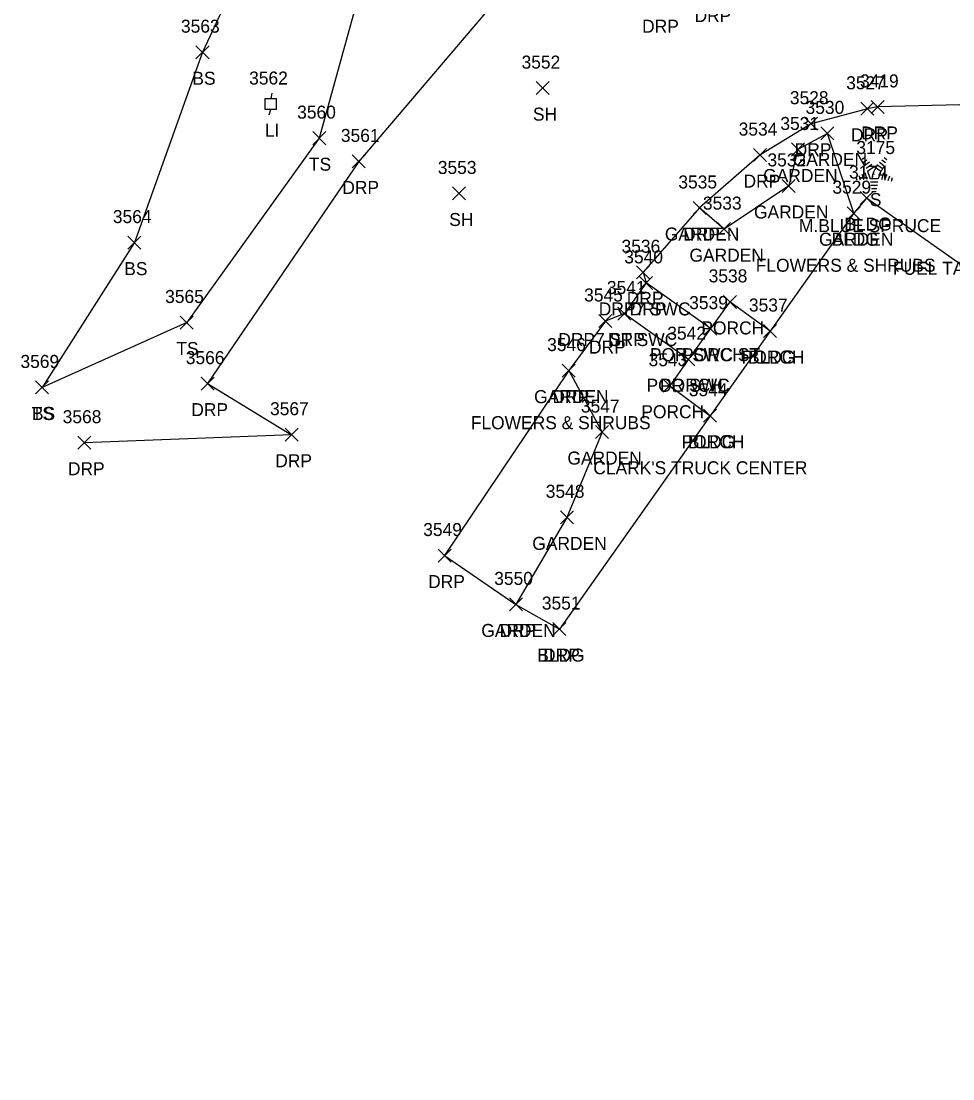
# Model space of a CAD drawing. Extents: x 1520648 to 1523413, y 732854 to 735518.
# Drawn here: x 1521497.2 to 1521640.4, y 733371.2 to 733533.8 of the extents above; entities that cross this region are included whole.
import ezdxf

# ---------------------------------------------------------------- set-up
doc = ezdxf.new("R2010")
doc.units = 0
for name, color, linetype in [('L_A', 7, 'Continuous'), ('L_C', 7, 'Continuous'), ('L_I', 7, 'Continuous'), ('L_TIC', 7, 'Continuous'), ('LAPB', 7, 'Continuous'), ('LBC', 7, 'Continuous'), ('LBF', 7, 'Continuous'), ('LELB', 7, 'Continuous'), ('LTC', 7, 'Continuous'), ('R_A', 7, 'Continuous'), ('R_C', 7, 'Continuous'), ('R_I', 7, 'Continuous'), ('R_TIC', 7, 'Continuous'), ('RDP', 7, 'Continuous'), ('RSW', 7, 'Continuous'), ('U_A', 7, 'Continuous'), ('U_C', 7, 'Continuous'), ('U_I', 7, 'Continuous'), ('ULP', 7, 'Continuous')]:
    doc.layers.add(name, color=color, linetype=linetype)

msp = doc.modelspace()

# ---------------------------------------------------------------- linework, layer by layer
at = {"layer": 'L_TIC'}
for points in [[(1521524.06, 733528.01), (1521526.06, 733530.01)], [(1521526.06, 733528.01), (1521524.06, 733530.01)], [(1521576.36, 733522.49), (1521578.36, 733524.49)], [(1521578.36, 733522.49), (1521576.36, 733524.49)], [(1521542.01, 733514.8), (1521544.01, 733516.8)], [(1521544.01, 733514.8), (1521542.01, 733516.8)], [(1521620.11, 733515.53), (1521622.11, 733517.53)], [(1521622.11, 733515.53), (1521620.11, 733517.53)], [(1521615.58, 733513.06), (1521617.58, 733515.06)], [(1521617.58, 733513.06), (1521615.58, 733515.06)], [(1521614.16, 733507.46), (1521616.16, 733509.46)], [(1521616.16, 733507.46), (1521614.16, 733509.46)], [(1521563.49, 733506.3), (1521565.49, 733508.3)], [(1521565.49, 733506.3), (1521563.49, 733508.3)], [(1521626.13, 733505.6), (1521628.13, 733507.6)], [(1521628.13, 733505.6), (1521626.13, 733507.6)], [(1521600.46, 733504.07), (1521602.46, 733506.07)], [(1521602.46, 733504.07), (1521600.46, 733506.07)], [(1521624.15, 733503.27), (1521626.15, 733505.27)], [(1521626.15, 733503.27), (1521624.15, 733505.27)], [(1521624.15, 733503.27), (1521626.15, 733505.27)], [(1521626.15, 733503.27), (1521624.15, 733505.27)], [(1521604.24, 733500.82), (1521606.24, 733502.82)], [(1521606.24, 733500.82), (1521604.24, 733502.82)], [(1521513.59, 733498.75), (1521515.59, 733500.75)], [(1521515.59, 733498.75), (1521513.59, 733500.75)], [(1521605.12, 733489.64), (1521607.12, 733491.64)], [(1521607.12, 733489.64), (1521605.12, 733491.64)], [(1521521.63, 733486.47), (1521523.63, 733488.47)], [(1521523.63, 733486.47), (1521521.63, 733488.47)], [(1521602.14, 733485.53), (1521604.14, 733487.53)], [(1521604.14, 733485.53), (1521602.14, 733487.53)], [(1521611.31, 733485.16), (1521613.31, 733487.16)], [(1521613.31, 733485.16), (1521611.31, 733487.16)], [(1521611.31, 733485.16), (1521613.31, 733487.16)], [(1521613.31, 733485.16), (1521611.31, 733487.16)], [(1521598.76, 733480.83), (1521600.76, 733482.83)], [(1521600.76, 733480.83), (1521598.76, 733482.83)], [(1521580.36, 733479.08), (1521582.36, 733481.08)], [(1521582.36, 733479.08), (1521580.36, 733481.08)], [(1521499.4, 733476.49), (1521501.4, 733478.49)], [(1521501.4, 733476.49), (1521499.4, 733478.49)], [(1521499.4, 733476.49), (1521501.4, 733478.49)], [(1521501.4, 733476.49), (1521499.4, 733478.49)], [(1521595.89, 733476.76), (1521597.89, 733478.76)], [(1521597.89, 733476.76), (1521595.89, 733478.76)], [(1521602.07, 733472.15), (1521604.07, 733474.15)], [(1521604.07, 733472.15), (1521602.07, 733474.15)], [(1521602.07, 733472.15), (1521604.07, 733474.15)], [(1521604.07, 733472.15), (1521602.07, 733474.15)], [(1521585.48, 733469.64), (1521587.48, 733471.64)], [(1521587.48, 733469.64), (1521585.48, 733471.64)], [(1521580.08, 733456.53), (1521582.08, 733458.53)], [(1521582.08, 733456.53), (1521580.08, 733458.53)], [(1521572.24, 733443.15), (1521574.24, 733445.15)], [(1521574.24, 733443.15), (1521572.24, 733445.15)], [(1521578.92, 733439.36), (1521580.92, 733441.36)], [(1521580.92, 733439.36), (1521578.92, 733441.36)]]:
    msp.add_lwpolyline(points, dxfattribs=at)
at = {"layer": 'LAPB'}
for points in [[(1521625.15, 733504.27), (1521621.11, 733516.53), (1521616.58, 733514.06), (1521615.16, 733508.46), (1521605.24, 733501.82), (1521601.46, 733505.07)], [(1521581.36, 733480.08), (1521586.48, 733470.64), (1521581.08, 733457.53), (1521573.24, 733444.15)]]:
    msp.add_lwpolyline(points, dxfattribs=at)
at = {"layer": 'LBC'}
msp.add_lwpolyline([(1521679.09, 733371.25), (1521662.93, 733382.5), (1521673.05, 733396.59), (1521696.23, 733429.21), (1521709.45, 733448.41), (1521685.68, 733465.22), (1521651.94, 733489.12), (1521627.13, 733506.6), (1521625.15, 733504.27), (1521612.31, 733486.16), (1521603.07, 733473.15), (1521579.92, 733440.36)], dxfattribs=at)
at = {"layer": 'LBF'}
msp.add_lwpolyline([(1521612.31, 733486.16), (1521606.12, 733490.64), (1521603.14, 733486.53), (1521599.76, 733481.83), (1521596.89, 733477.76), (1521603.07, 733473.15)], dxfattribs=at)
at = {"layer": 'LELB'}
for points in [[(1521715.31, 733596.64), (1521690.84, 733596.56), (1521683.72, 733580.69), (1521656.58, 733563.65), (1521634.24, 733563.97), (1521591.91, 733575.22), (1521564.43, 733565.64), (1521537.4, 733555.4), (1521525.06, 733529.01), (1521514.59, 733499.75), (1521500.4, 733477.49)], [(1521703.63, 733583.19), (1521701.66, 733579.65), (1521688.64, 733572.91), (1521656.52, 733553.66), (1521632.6, 733553.92), (1521594.7, 733555.4), (1521573.72, 733552.45), (1521549.54, 733539.55), (1521543.01, 733515.8), (1521522.63, 733487.47), (1521500.4, 733477.49)]]:
    msp.add_lwpolyline(points, dxfattribs=at)
at = {"layer": 'LTC'}
for p, q in [((1521626.45, 733512.57), (1521626.8, 733512.83)), ((1521626.66, 733512.11), (1521627.19, 733512.49)), ((1521626.87, 733511.64), (1521627.57, 733512.15)), ((1521629.1, 733512.12), (1521629.78, 733511.62)), ((1521629.48, 733512.46), (1521630.03, 733512.06)), ((1521629.85, 733512.81), (1521630.27, 733512.51)), ((1521626.39, 733510.28), (1521626.66, 733509.45)), ((1521626.85, 733510.5), (1521627.18, 733509.48)), ((1521627.08, 733511.17), (1521627.96, 733511.81)), ((1521627.3, 733510.72), (1521628.31, 733511.45)), ((1521627.3, 733510.72), (1521627.69, 733509.53)), ((1521628.31, 733511.45), (1521629.31, 733510.73)), ((1521628.73, 733511.77), (1521629.54, 733511.18)), ((1521629.31, 733510.73), (1521628.92, 733509.53)), ((1521629.75, 733510.46), (1521629.41, 733509.42)), ((1521625.48, 733509.85), (1521625.63, 733509.38)), ((1521625.94, 733510.07), (1521626.15, 733509.42)), ((1521628.92, 733509.53), (1521627.69, 733509.53)), ((1521628.88, 733509.03), (1521627.74, 733509.03)), ((1521630.19, 733510.21), (1521629.91, 733509.32)), ((1521630.64, 733509.96), (1521630.4, 733509.23)), ((1521631.08, 733509.71), (1521630.89, 733509.13)), ((1521628.8, 733508.53), (1521627.81, 733508.53)), ((1521628.71, 733508.03), (1521627.88, 733508.03)), ((1521628.63, 733507.53), (1521627.95, 733507.53))]:
    msp.add_line(p, q, dxfattribs=at)
at = {"layer": 'R_TIC'}
for points in [[(1521626.26, 733519.31), (1521628.26, 733521.31)], [(1521628.26, 733519.31), (1521626.26, 733521.31)], [(1521627.82, 733519.6), (1521629.82, 733521.6)], [(1521629.82, 733519.6), (1521627.82, 733521.6)], [(1521617.6, 733517.02), (1521619.6, 733519.02)], [(1521619.6, 733517.02), (1521617.6, 733519.02)], [(1521609.73, 733512.2), (1521611.73, 733514.2)], [(1521611.73, 733512.2), (1521609.73, 733514.2)], [(1521548.07, 733511.22), (1521550.07, 733513.22)], [(1521550.07, 733511.22), (1521548.07, 733513.22)], [(1521600.46, 733504.07), (1521602.46, 733506.07)], [(1521602.46, 733504.07), (1521600.46, 733506.07)], [(1521591.79, 733494.19), (1521593.79, 733496.19)], [(1521593.79, 733494.19), (1521591.79, 733496.19)], [(1521592.24, 733492.56), (1521594.24, 733494.56)], [(1521594.24, 733492.56), (1521592.24, 733494.56)], [(1521592.24, 733492.56), (1521594.24, 733494.56)], [(1521594.24, 733492.56), (1521592.24, 733494.56)], [(1521588.92, 733487.85), (1521590.92, 733489.85)], [(1521590.92, 733487.85), (1521588.92, 733489.85)], [(1521588.92, 733487.85), (1521590.92, 733489.85)], [(1521590.92, 733487.85), (1521588.92, 733489.85)], [(1521585.98, 733486.7), (1521587.98, 733488.7)], [(1521587.98, 733486.7), (1521585.98, 733488.7)], [(1521602.14, 733485.53), (1521604.14, 733487.53)], [(1521604.14, 733485.53), (1521602.14, 733487.53)], [(1521598.76, 733480.83), (1521600.76, 733482.83)], [(1521600.76, 733480.83), (1521598.76, 733482.83)], [(1521580.36, 733479.08), (1521582.36, 733481.08)], [(1521582.36, 733479.08), (1521580.36, 733481.08)], [(1521524.85, 733477.08), (1521526.85, 733479.08)], [(1521526.85, 733477.08), (1521524.85, 733479.08)], [(1521505.88, 733468), (1521507.88, 733470)], [(1521507.88, 733468), (1521505.88, 733470)], [(1521537.75, 733469.23), (1521539.75, 733471.23)], [(1521539.75, 733469.23), (1521537.75, 733471.23)], [(1521561.26, 733450.66), (1521563.26, 733452.66)], [(1521563.26, 733450.66), (1521561.26, 733452.66)], [(1521572.24, 733443.15), (1521574.24, 733445.15)], [(1521574.24, 733443.15), (1521572.24, 733445.15)], [(1521578.92, 733439.36), (1521580.92, 733441.36)], [(1521580.92, 733439.36), (1521578.92, 733441.36)]]:
    msp.add_lwpolyline(points, dxfattribs=at)
at = {"layer": 'RDP'}
for points in [[(1521575.01, 733542.71), (1521549.07, 733512.22), (1521525.85, 733478.08), (1521538.75, 733470.23), (1521506.88, 733469)], [(1521678.96, 733392.35), (1521701.59, 733424.52), (1521714.94, 733443.08), (1521727.93, 733435.38), (1521734.93, 733458.92), (1521724.21, 733475.33), (1521709.2, 733487.68), (1521683.55, 733505.62), (1521674.22, 733511.48), (1521662.29, 733517.33), (1521649.85, 733521.14), (1521628.82, 733520.6), (1521627.26, 733520.31), (1521618.6, 733518.02), (1521610.73, 733513.2), (1521601.46, 733505.07), (1521592.79, 733495.19), (1521593.24, 733493.56)], [(1521589.92, 733488.85), (1521586.98, 733487.7), (1521581.36, 733480.08), (1521562.26, 733451.66), (1521573.24, 733444.15), (1521579.92, 733440.36)]]:
    msp.add_lwpolyline(points, dxfattribs=at)
at = {"layer": 'RSW'}
msp.add_lwpolyline([(1521603.14, 733486.53), (1521593.24, 733493.56), (1521589.92, 733488.85), (1521599.76, 733481.83)], dxfattribs=at)
at = {"layer": 'ULP'}
for p, q in [((1521534.71, 733520.21), (1521534.71, 733521.88)), ((1521534.71, 733521.88), (1521536.37, 733521.88)), ((1521535.71, 733522.71), (1521535.54, 733521.88)), ((1521536.37, 733521.88), (1521536.37, 733520.21)), ((1521536.37, 733520.21), (1521534.71, 733520.21)), ((1521535.29, 733519.38), (1521535.54, 733520.21)), ((1521535.54, 733521.04), (1521535.54, 733521.04))]:
    msp.add_line(p, q, dxfattribs=at)

# ---------------------------------------------------------------- texts
at = {"layer": 'L_A'}
for s, p in [('BS', (1521523.5, 733524.01)), ('SH', (1521575.85, 733518.49)), ('GARDEN', (1521615.78, 733511.53)), ('TS', (1521541.42, 733510.8)), ('GARDEN', (1521611.24, 733509.06)), ('S', (1521627.64, 733505.36)), ('GARDEN', (1521609.83, 733503.46)), ('SH', (1521562.98, 733502.3)), ('BLDG', (1521623.72, 733501.6)), ('GARDEN', (1521596.13, 733500.07)), ('GARDEN', (1521619.82, 733499.27)), ('BLDG', (1521621.74, 733499.27)), ('GARDEN', (1521599.91, 733496.82)), ('BS', (1521513.03, 733494.75)), ('PORCH', (1521601.74, 733485.64)), ('TS', (1521521.04, 733482.47)), ('PORCH', (1521598.76, 733481.53)), ('PORCH', (1521607.93, 733481.16)), ('BLDG', (1521608.9, 733481.16)), ('PORCH', (1521595.38, 733476.83)), ('GARDEN', (1521576.03, 733475.08)), ('TS', (1521498.81, 733472.49)), ('BS', (1521498.84, 733472.49)), ('PORCH', (1521592.51, 733472.76)), ('PORCH', (1521598.69, 733468.15)), ('BLDG', (1521599.66, 733468.15)), ('GARDEN', (1521581.15, 733465.64)), ('GARDEN', (1521575.75, 733452.53)), ('GARDEN', (1521567.91, 733439.15)), ('BLDG', (1521576.51, 733435.36))]:
    msp.add_text(s, height=2, dxfattribs=at).set_placement(p)
at = {"layer": 'L_C'}
for s, p in [('M.BLUE SPRUCE', (1521616.74, 733501.36)), ('FLOWERS & SHRUBS', (1521610.1, 733495.27)), ("CLARK'S TRUCK CENTER", (1521585.13, 733464.15))]:
    msp.add_text(s, height=2, dxfattribs=at).set_placement(p)
at = {"layer": 'L_I'}
for s, p in [('3563', (1521521.75, 733532.01)), ('3552', (1521574.1, 733526.49)), ('3560', (1521539.61, 733518.8)), ('3530', (1521617.76, 733519.53)), ('3531', (1521613.88, 733517.06)), ('3175', (1521625.56, 733513.36)), ('3553', (1521561.23, 733510.3)), ('3532', (1521611.9, 733511.46)), ('3174', (1521624.44, 733509.6)), ('3535', (1521598.2, 733508.07)), ('3529', (1521621.88, 733507.27)), ('3529', (1521621.88, 733507.27)), ('3533', (1521601.98, 733504.82)), ('3564', (1521511.28, 733502.75)), ('3538', (1521602.86, 733493.64)), ('3565', (1521519.32, 733490.47)), ('3539', (1521599.87, 733489.53)), ('3537', (1521609.05, 733489.16)), ('3537', (1521609.05, 733489.16)), ('3542', (1521596.5, 733484.83)), ('3546', (1521578.04, 733483.08)), ('3543', (1521593.63, 733480.76)), ('3569', (1521497.08, 733480.49)), ('3569', (1521497.08, 733480.49)), ('3544', (1521599.81, 733476.15)), ('3544', (1521599.81, 733476.15)), ('3547', (1521583.22, 733473.64)), ('3548', (1521577.82, 733460.53)), ('3550', (1521569.9, 733447.15)), ('3551', (1521577.22, 733443.36))]:
    msp.add_text(s, height=2, dxfattribs=at).set_placement(p)
at = {"layer": 'LTC'}
msp.add_text('.', height=1.04, rotation=270, dxfattribs=at).set_placement((1521628.2, 733510.47))
at = {"layer": 'R_A'}
for s, p in [('DRP', (1521600.69, 733533.65)), ('DRP', (1521592.63, 733532)), ('DRP', (1521624.75, 733515.31)), ('DRP', (1521626.3, 733515.6)), ('DRP', (1521616.09, 733513.02)), ('DRP', (1521546.55, 733507.22)), ('DRP', (1521608.22, 733508.2)), ('DRP', (1521598.95, 733500.07)), ('DRP', (1521590.27, 733490.19)), ('DRP7 SWC', (1521585.97, 733488.56)), ('DRP', (1521590.73, 733488.56)), ('DRP7 ST SWC', (1521579.75, 733483.85)), ('DRP', (1521584.47, 733482.7)), ('DRP', (1521587.4, 733483.85)), ('POR SWC ST', (1521593.82, 733481.53)), ('POR SWC', (1521593.31, 733476.83)), ('DRP', (1521578.85, 733475.08)), ('DRP', (1521523.34, 733473.08)), ('DRP', (1521536.24, 733465.23)), ('DRP', (1521504.37, 733464)), ('DRP', (1521559.74, 733446.66)), ('DRP', (1521570.73, 733439.15)), ('DRP', (1521577.41, 733435.36))]:
    msp.add_text(s, height=2, dxfattribs=at).set_placement(p)
at = {"layer": 'R_C'}
msp.add_text('FLOWERS & SHRUBS', height=2, dxfattribs=at).set_placement((1521566.3, 733471.08))
at = {"layer": 'R_I'}
for s, p in [('3527', (1521624, 733523.31)), ('3419', (1521626.12, 733523.6)), ('3528', (1521615.34, 733521.02)), ('3561', (1521546.33, 733515.22)), ('3534', (1521607.47, 733516.2)), ('3535', (1521598.2, 733508.07)), ('3536', (1521589.47, 733498.19)), ('3540', (1521589.89, 733496.56)), ('3540', (1521589.89, 733496.56)), ('3545', (1521583.72, 733490.7)), ('3541', (1521587.22, 733491.85)), ('3541', (1521587.22, 733491.85)), ('3539', (1521599.87, 733489.53)), ('3542', (1521596.5, 733484.83)), ('3546', (1521578.04, 733483.08)), ('3566', (1521522.49, 733481.08)), ('3567', (1521535.44, 733473.23)), ('3568', (1521503.57, 733472)), ('3549', (1521558.99, 733454.66)), ('3550', (1521569.9, 733447.15)), ('3551', (1521577.22, 733443.36))]:
    msp.add_text(s, height=2, dxfattribs=at).set_placement(p)
at = {"layer": 'U_A'}
msp.add_text('LI', height=2, dxfattribs=at).set_placement((1521534.64, 733516.04))
at = {"layer": 'U_C'}
msp.add_text('FUEL TANK FILLER', height=2, dxfattribs=at).set_placement((1521631.18, 733494.8))
at = {"layer": 'U_I'}
msp.add_text('3562', height=2, dxfattribs=at).set_placement((1521532.23, 733524.04))

doc.saveas('drawing.dxf')
